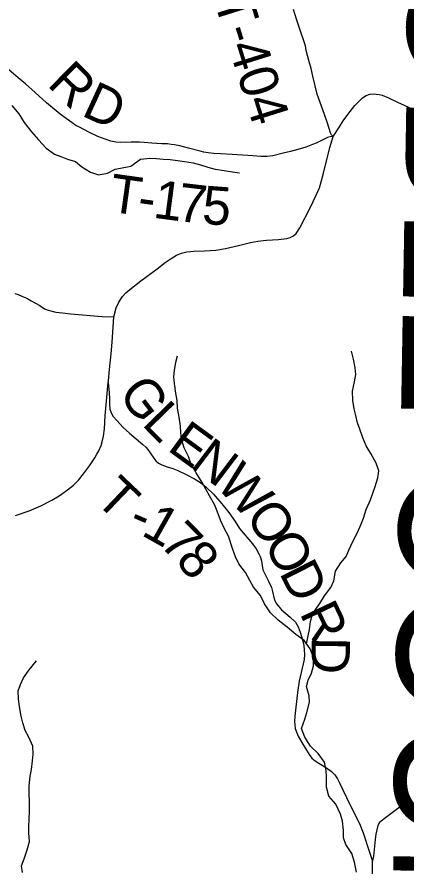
# Model space of a CAD drawing. Extents: x 0 to 191, y 0 to 55.
# Drawn here: x 149.068 to 149.356, y 23.985 to 24.615 of the extents above; entities that cross this region are included whole.
import ezdxf

# ---------------------------------------------------------------- set-up
doc = ezdxf.new("R2010")
doc.units = 0
for name, color, linetype in [('GM_X_County_Road', 7, 'Continuous'), ('GM_X_County_Text', 7, 'Continuous'), ('GM_X_Minor_River', 7, 'Continuous'), ('GM_X_State_Route', 7, 'Continuous'), ('GM_X_Township_Road', 7, 'Continuous'), ('GM_X_Township_Road_Text', 7, 'Continuous')]:
    doc.layers.add(name, color=color, linetype=linetype)

msp = doc.modelspace()

# ---------------------------------------------------------------- linework, layer by layer
at = {"layer": 'GM_X_County_Road'}
msp.add_lwpolyline([(149.06626, 24.41007), (149.06871, 24.40927), (149.07133, 24.40816), (149.07502, 24.40651), (149.07828, 24.40463), (149.08481, 24.40105), (149.08836, 24.39874), (149.09094, 24.3977), (149.09675, 24.39619), (149.10149, 24.39558), (149.10761, 24.39492), (149.13111, 24.39302), (149.13959, 24.39266)], dxfattribs=at)
at = {"layer": 'GM_X_Minor_River'}
for points in [[(149.06405, 24.5496), (149.06919, 24.54353), (149.07319, 24.53708), (149.07872, 24.53007), (149.08385, 24.5242), (149.08937, 24.51794), (149.09565, 24.5134), (149.10039, 24.51171), (149.10533, 24.50982), (149.11122, 24.50794), (149.11597, 24.50415), (149.12243, 24.50018), (149.12832, 24.49811), (149.13496, 24.49927), (149.14064, 24.50233), (149.15241, 24.50465)], [(149.15241, 24.50465), (149.15955, 24.50965), (149.16635, 24.51049), (149.17146, 24.51037), (149.1762, 24.50967), (149.18149, 24.50954), (149.18699, 24.50866), (149.1921, 24.50797), (149.19855, 24.50691), (149.20405, 24.50546), (149.20937, 24.50382), (149.21487, 24.50237), (149.2215, 24.50132), (149.22775, 24.50045), (149.23287, 24.49956)], [(149.2827, 24.15006), (149.28486, 24.16054), (149.28573, 24.16644), (149.28717, 24.17234), (149.29255, 24.17999), (149.29608, 24.18554), (149.30072, 24.19186), (149.30293, 24.19682), (149.30417, 24.20385), (149.30825, 24.20998), (149.31197, 24.21477), (149.31418, 24.21954), (149.31712, 24.22603), (149.32044, 24.23271), (149.32302, 24.23824), (149.32485, 24.2432), (149.32703, 24.24968), (149.33016, 24.25674), (149.3318, 24.2617), (149.33362, 24.26684), (149.33562, 24.27313), (149.33631, 24.27845), (149.33435, 24.28412), (149.33047, 24.29128), (149.327, 24.29693), (149.32446, 24.30278), (149.3223, 24.30921), (149.32054, 24.31412), (149.31933, 24.31942), (149.31795, 24.32433), (149.31711, 24.33058), (149.31683, 24.3376), (149.31826, 24.34445), (149.31932, 24.34978), (149.31869, 24.35489), (149.31747, 24.36133), (149.31607, 24.3672)], [(149.18482, 24.35283), (149.18569, 24.3591), (149.18695, 24.36386)], [(149.31966, 23.98041), (149.31824, 23.98779), (149.31627, 23.99421), (149.31183, 24.00098), (149.31007, 24.00589), (149.31, 24.01139), (149.30935, 24.01821), (149.30796, 24.0235), (149.30446, 24.03085), (149.29928, 24.03686), (149.29749, 24.04347), (149.29759, 24.05125), (149.29734, 24.05599), (149.29594, 24.06223), (149.29132, 24.06843), (149.28557, 24.07405), (149.28133, 24.08064), (149.27898, 24.08706), (149.28135, 24.09392), (149.28299, 24.09906), (149.28497, 24.10667), (149.28472, 24.11141), (149.28275, 24.11821), (149.28382, 24.12297), (149.2864, 24.12812), (149.28785, 24.13364), (149.28796, 24.1399), (149.28542, 24.14613), (149.28099, 24.15253), (149.27469, 24.157), (149.26819, 24.16242), (149.2617, 24.16746), (149.25596, 24.17289), (149.25152, 24.17967), (149.24842, 24.18589), (149.24342, 24.19208), (149.24052, 24.19698), (149.23742, 24.20301), (149.23242, 24.2094), (149.2299, 24.21449), (149.22794, 24.21997), (149.22478, 24.2298), (149.22168, 24.23583), (149.21896, 24.24187), (149.21642, 24.24848), (149.21427, 24.25338), (149.2106, 24.25979), (149.20808, 24.26469), (149.20536, 24.26978), (149.20073, 24.27693), (149.19686, 24.2839), (149.1951, 24.28901), (149.1918, 24.29542), (149.19001, 24.30185), (149.18938, 24.30677), (149.18913, 24.31151), (149.1881, 24.31814), (149.18688, 24.32496), (149.18662, 24.33065), (149.18579, 24.33614), (149.18476, 24.34315), (149.18432, 24.34808), (149.18482, 24.35283)], [(149.07181, 23.98019), (149.07123, 23.98513), (149.07311, 23.99045), (149.07537, 23.99711), (149.07706, 24.00319), (149.07667, 24.00965), (149.07666, 24.01439), (149.07683, 24.0199), (149.07701, 24.0256), (149.07718, 24.03282), (149.07698, 24.03851), (149.07696, 24.04459), (149.0777, 24.05162), (149.07864, 24.05675), (149.07938, 24.06302), (149.07994, 24.06815), (149.07954, 24.07404), (149.07668, 24.08068), (149.07401, 24.08561), (149.07229, 24.0913), (149.07095, 24.09624), (149.06979, 24.10345), (149.06902, 24.10877), (149.06882, 24.11504), (149.07032, 24.11979), (149.07277, 24.12474), (149.07693, 24.13064), (149.08223, 24.1373)]]:
    msp.add_lwpolyline(points, dxfattribs=at)
at = {"layer": 'GM_X_State_Route'}
msp.add_lwpolyline([(149.06662, 24.24513), (149.07686, 24.24868), (149.08544, 24.25243), (149.09367, 24.25665), (149.09902, 24.25979), (149.10534, 24.26431), (149.10966, 24.26776), (149.11352, 24.27151), (149.11727, 24.27609), (149.12154, 24.28221), (149.1256, 24.28802), (149.1272, 24.29064), (149.12848, 24.29331), (149.13018, 24.29727), (149.13111, 24.3), (149.13208, 24.30406), (149.13275, 24.30956), (149.13332, 24.31913), (149.13551, 24.34385), (149.13563, 24.34509), (149.1365, 24.35368), (149.13764, 24.3653), (149.13846, 24.37389), (149.13913, 24.38515), (149.13959, 24.39266), (149.1414, 24.39935), (149.14329, 24.40361), (149.14617, 24.40783), (149.14859, 24.41055), (149.15157, 24.41312), (149.1598, 24.4195), (149.17182, 24.42839), (149.17785, 24.43307), (149.18212, 24.43606), (149.18618, 24.43837), (149.18993, 24.43986), (149.19384, 24.44094), (149.19651, 24.4413), (149.19898, 24.44146), (149.20685, 24.44161), (149.21533, 24.44228), (149.22243, 24.44336), (149.2321, 24.44578), (149.24104, 24.44788), (149.24649, 24.44876), (149.25308, 24.44953), (149.26182, 24.4502), (149.26799, 24.45092), (149.27056, 24.45164), (149.27308, 24.45287), (149.27503, 24.45467), (149.27781, 24.45868), (149.28547, 24.4737), (149.28994, 24.48306), (149.29226, 24.48845), (149.29359, 24.49293), (149.29539, 24.4993), (149.30002, 24.51833), (149.30256, 24.52657), (149.30702, 24.53376), (149.30989, 24.53828), (149.31329, 24.54301), (149.31853, 24.54949), (149.32409, 24.5553), (149.32697, 24.5571), (149.32959, 24.55792), (149.33216, 24.55833), (149.33648, 24.55787), (149.3389, 24.55715), (149.34342, 24.5552), (149.35016, 24.55206), (149.36116, 24.54718)], dxfattribs=at)
at = {"layer": 'GM_X_Township_Road'}
for points in [[(149.30256, 24.52657), (149.30126, 24.52784), (149.30038, 24.52918), (149.29812, 24.53653), (149.29596, 24.54291), (149.29066, 24.5579), (149.28738, 24.5714), (149.28607, 24.57694), (149.28429, 24.58304), (149.28252, 24.59036), (149.28182, 24.59383), (149.28069, 24.59756), (149.27854, 24.60415), (149.27523, 24.61372), (149.27303, 24.62082)], [(149.30256, 24.52657), (149.30018, 24.52645), (149.29814, 24.52588), (149.29277, 24.52306), (149.2899, 24.52173), (149.28717, 24.52054), (149.28219, 24.51874), (149.27631, 24.51696), (149.27077, 24.51544), (149.26531, 24.51414), (149.25757, 24.51224), (149.25339, 24.51171), (149.2487, 24.51185), (149.24274, 24.51233), (149.22744, 24.51316), (149.2189, 24.51363), (149.21392, 24.51405), (149.20967, 24.51449), (149.20644, 24.51497), (149.20365, 24.51565), (149.19511, 24.5179), (149.18856, 24.51954), (149.1847, 24.52031), (149.18233, 24.52075), (149.17957, 24.52108), (149.17536, 24.5212), (149.1678, 24.52152), (149.16222, 24.52209), (149.1587, 24.52232), (149.15267, 24.52232), (149.14485, 24.52203), (149.14108, 24.52226), (149.1374, 24.52309), (149.13322, 24.52449), (149.12791, 24.52665), (149.12106, 24.52992), (149.11433, 24.53344), (149.11142, 24.53487), (149.10869, 24.53662), (149.09986, 24.54305), (149.08963, 24.55168), (149.08126, 24.55919), (149.07411, 24.56562), (149.06866, 24.57004), (149.06181, 24.576)], [(149.13551, 24.34385), (149.1363, 24.33625), (149.1364, 24.33219), (149.1364, 24.32751), (149.13681, 24.32411), (149.13774, 24.32149), (149.13923, 24.31877), (149.1419, 24.31578), (149.14662, 24.31063), (149.15131, 24.30627), (149.16129, 24.29784), (149.16355, 24.29589), (149.16504, 24.29419), (149.16926, 24.28776), (149.17075, 24.28586), (149.17283, 24.28411), (149.17536, 24.2829), (149.17937, 24.28147), (149.18349, 24.28021), (149.18728, 24.27867), (149.19376, 24.27548), (149.19958, 24.27235), (149.20398, 24.26961), (149.20815, 24.26631), (149.21353, 24.26115), (149.2199, 24.25384), (149.22507, 24.24753), (149.22968, 24.24072), (149.23303, 24.23561), (149.24253, 24.22413), (149.24522, 24.22045), (149.24731, 24.21688), (149.2483, 24.21479), (149.24918, 24.2115), (149.24984, 24.20815), (149.25022, 24.20491), (149.25445, 24.19645), (149.25664, 24.19169), (149.25747, 24.18876), (149.25873, 24.18348), (149.25989, 24.18041), (149.26154, 24.1781), (149.26412, 24.17525), (149.27043, 24.16986), (149.27439, 24.16613), (149.27637, 24.16256), (149.27807, 24.15871), (149.27972, 24.15289), (149.28065, 24.14877), (149.28103, 24.14559), (149.28114, 24.14202), (149.28087, 24.13828), (149.2773, 24.12219), (149.27593, 24.11395), (149.274, 24.09638), (149.27384, 24.09231), (149.27395, 24.08951), (149.27433, 24.08704), (149.27543, 24.08385), (149.27647, 24.08144), (149.27928, 24.07671), (149.28471, 24.06781), (149.28653, 24.06507), (149.289, 24.06304), (149.29191, 24.06139), (149.29757, 24.05793), (149.3013, 24.05524), (149.30366, 24.05266), (149.30569, 24.04974), (149.30723, 24.04689), (149.31481, 24.03058), (149.32201, 24.01657), (149.3247, 24.00954), (149.32942, 23.99526), (149.33173, 23.98861)], [(149.33173, 23.98861), (149.33266, 23.99224), (149.33387, 24.00471), (149.33442, 24.00877), (149.33501, 24.01187), (149.33576, 24.01507), (149.33715, 24.01791), (149.34222, 24.02186), (149.35223, 24.02928), (149.3595, 24.03603)], [(149.33134, 23.96168), (149.33173, 23.98861)]]:
    msp.add_lwpolyline(points, dxfattribs=at)

# ---------------------------------------------------------------- texts
at = {"layer": 'GM_X_County_Text'}
msp.add_text('NOBLE COUNTY', height=0.094697, rotation=269.02137, dxfattribs=at).set_placement((149.3601, 24.74846))
at = {"layer": 'GM_X_Township_Road_Text'}
for s, height, rotation, p in [('T-404', 0.028409, 287.43323, (149.21372, 24.62786)), ('R', 0.02841, 315.51334, (149.0895, 24.56478)), ('D', 0.02841, 335.33596, (149.1148, 24.54247)), ('T', 0.02841, 352.0893, (149.13535, 24.47092)), ('1', 0.02841, 352.50772, (149.16818, 24.46638)), ('7', 0.02841, 353.35901, (149.18599, 24.46404)), ('5', 0.02841, 355.65134, (149.2046, 24.4619)), ('-', 0.02841, 352.17622, (149.15644, 24.46799)), ('G', 0.02841, 307.6932, (149.14218, 24.33529)), ('L', 0.02841, 314.28002, (149.1598, 24.31282)), ('E', 0.02841, 323.85266, (149.17855, 24.29421)), ('N', 0.02841, 322.8161, (149.1956, 24.28176)), ('W', 0.02841, 313.30756, (149.21459, 24.26748)), ('T', 0.02841, 316.3759, (149.12474, 24.25609)), ('O', 0.02841, 305.4928, (149.23652, 24.24432)), ('1', 0.02841, 330.51525, (149.15924, 24.23115)), ('-', 0.02841, 336.70297, (149.14925, 24.2354)), ('7', 0.02841, 314.44804, (149.1728, 24.22382)), ('O', 0.02841, 297.78535, (149.2505, 24.22482)), ('8', 0.02841, 309.57171, (149.18463, 24.2118)), ('D', 0.02841, 296.85015, (149.2621, 24.20282)), ('R', 0.02841, 295.46536, (149.27725, 24.17286)), ('D', 0.02841, 269.32244, (149.28656, 24.15512))]:
    msp.add_text(s, height=height, rotation=rotation, dxfattribs=at).set_placement(p)

doc.saveas('drawing.dxf')
